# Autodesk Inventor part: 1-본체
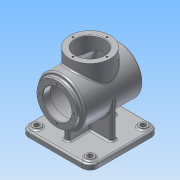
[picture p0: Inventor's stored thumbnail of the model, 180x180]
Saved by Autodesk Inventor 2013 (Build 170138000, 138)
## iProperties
Created: 2015-07
Part Number: 1-본체
Material: 알루미늄 6061
Document SubType Name: Modeling
Designer: Administrator
Density: 2.71 g/cm^3
Mass: 1279.26 g
Surface Area: 1271.88 cm^2
Volume: 472.05 cm^3
Author: Administrator
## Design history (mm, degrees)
sketch "스케치1"
  geometry: C1 r 45 at (0, 0); 1 further point
  constraints: 1 centre point, 1 coincident
  dimensions: "d0" = 90 diameter of C1
extrude "돌출1" new body sketch "스케치1" stored distance "d2" = 110; taper "d3" = 0 deg
node "작업 평면1"
sketch "스케치2"
  geometry: L1 (-50, 65)-(50, 65); L2 (65, 50)-(65, -50); L3 (50, -65)-(-50, -65); L4 (-65, -50)-(-65, 50); A1 r 15 centre (-50, 50) between (-50, 65) and (-65, 50); A2 r 15 centre (-50, -50) between (-65, -50) and (-50, -65); A3 r 15 centre (50, -50) between (50, -65) and (65, -50); A4 r 15 centre (50, 50) between (65, 50) and (50, 65); 6 further points
  constraints: 8 end point, 8 point on circle, 8 point on line, 8 tangent, 4 centre point, 3 equal radius, 2 parallel, 1 horizontal, 1 midpoint, 1 perpendicular, 1 vertical alignment
  dimensions: "d5" = 130 distance between parallel lines of L2 L4; "d7" = 65 distance from line of L3 point (0, 0); "d8" = 130 distance between parallel lines of L3 L1; "d11" = 15 radius of A1
extrude "돌출2" join sketch "스케치2" distance "d9" = 10; taper "d10" = 0 deg
sketch "스케치3"
  geometry: L1 (-50, -68)-(-65, -68) reference; L2 (50, -68)-(-50, -68) reference; L3 (65, -68)-(50, -68) reference; L4 (-45, -68)-(-45, 0); L5 (-45, 0)-(45, 0); L6 (45, 0)-(45, -68); C1 r 45 at (0, 0) reference; 2 further points
  constraints: 6 end point, 3 perpendicular, 2 point on line, 1 coincident, 1 midpoint, 1 tangent
  dimensions: "d14" = 68 distance between parallel lines of L2 L5
extrude "돌출3" join sketch "스케치3" stored distance "d16" = 10; taper "d17" = 0 deg
sketch "스케치4"
  geometry: L1 (-68, 50)-(-68, 65) reference; L2 (-68, -50)-(-68, 50) reference; L3 (-68, -65)-(-68, -50) reference; L4 (45, 55)-(-45, 55) reference; L5 (-45, -55)-(45, -55) reference; L6 (-68, 45)-(2, 45); L7 (2, 45)-(2, -45); L8 (2, -45)-(-68, -45); 2 further points
  constraints: 6 end point, 2 perpendicular, 2 point on line, 1 horizontal alignment, 1 midpoint, 1 parallel
  dimensions: "d18" = 90 distance between parallel lines of L8 L6; "d20" = 70 distance between parallel lines of L2 L7
extrude "돌출4" join sketch "스케치4" stored distance "d21" = 10; taper "d22" = 0 deg
sketch "스케치5"
  geometry: C1 r 38 at (0, 0); 1 further point
  constraints: 1 centre point, 1 coincident
  dimensions: "d23" = 76 diameter of C1
extrude "돌출5" join sketch "스케치5" distance "d25" = 62; taper "d26" = 0 deg
sketch "스케치6"
  geometry: C1 r 38 at (0, 0); 1 further point
  constraints: 1 centre point, 1 coincident
  dimensions: "d27" = 76 diameter of C1
extrude "돌출6" join sketch "스케치6" distance "d29" = 62; taper "d30" = 0 deg
sketch "스케치7"
  geometry: L1 (0, 48)-(0, -48); L2 (0, 48)-(40, 48); L3 (40, 48)-(40, -48); L4 (40, -48)-(0, -48); 2 further points
  constraints: 8 end point, 2 perpendicular, 1 coincident, 1 midpoint, 1 parallel, 1 vertical
  dimensions: "d67" = 96 distance of L1.start L1.end; "d69" = 80 diameter of L3 L1
revolve "회전1" sketch "스케치7" stored, may be unused: angle "d70" = 90 deg
hole "구멍5" diameter "d73" = 54; stored, may be unused: countersink angle "d77" = 90 deg, drill point angle "d79" = 118 deg; dims "d71" = 10, "d72" = 10, "d74" = 6, "d75" = 4, "d76" = 2, "d78" = 14
hole "구멍6" diameter "d82" = 54; stored, may be unused: countersink angle "d86" = 90 deg, drill point angle "d88" = 118 deg; dims "d80" = 10, "d81" = 10, "d83" = 6, "d84" = 4, "d85" = 2, "d87" = 30
sketch "스케치8"
  geometry: 2 further points
  constraints: 1 vertical alignment
  dimensions: "d89" = 32 distance of point (0, 0) point (0, 32)
hole "구멍7" sketch "스케치8" at (0, 32) diameter "d90" = 3.242; stored, may be unused: countersink angle "d94" = 90 deg, drill point angle "d96" = 118 deg; dims "d91" = 8, "d92" = 4, "d93" = 2, "d95" = 10
sketch "스케치9"
  geometry: 2 further points
  constraints: 1 vertical alignment
  dimensions: "d100" = 32 distance of point (0, 0) point (0, 32)
hole "구멍8" sketch "스케치9" at (0, 32) diameter "d101" = 3.242; stored, may be unused: countersink angle "d105" = 90 deg, drill point angle "d107" = 118 deg; dims "d102" = 8, "d103" = 4, "d104" = 2, "d106" = 10
sketch "스케치10"
  geometry: C1 r 7.5 at (-50, 50); C2 r 7.5 at (50, 50); C3 r 7.5 at (50, -50); C4 r 7.5 at (-50, -50); 1 further point
  constraints: 4 centre point, 3 equal radius, 2 horizontal alignment, 2 vertical alignment
  dimensions: "d111" = 100 distance of C2.centre C1.centre; "d113" = 50 horizontal distance of C2.centre point (0, 0); "d114" = 100 distance of C3.centre C2.centre; "d115" = 50 horizontal distance of C3.centre point (0, 0); "d116" = 15 diameter of C2
extrude "돌출7" join sketch "스케치10" distance "d117" = 3; taper "d118" = 0 deg
hole "구멍9" diameter "d121" = 10; stored, may be unused: countersink angle "d125" = 90 deg, drill point angle "d127" = 118 deg; dims "d119" = 10, "d120" = 10, "d122" = 10, "d123" = 4, "d124" = 2, "d126" = 10
hole "구멍10" diameter "d130" = 10; stored, may be unused: countersink angle "d134" = 90 deg, drill point angle "d136" = 118 deg; dims "d128" = 10, "d129" = 10, "d131" = 10, "d132" = 4, "d133" = 2, "d135" = 10
hole "구멍11" diameter "d139" = 10; stored, may be unused: countersink angle "d143" = 90 deg, drill point angle "d145" = 118 deg; dims "d137" = 10, "d138" = 10, "d140" = 10, "d141" = 4, "d142" = 2, "d144" = 10
hole "구멍12" diameter "d148" = 10; stored, may be unused: countersink angle "d152" = 90 deg, drill point angle "d154" = 118 deg; dims "d146" = 10, "d147" = 10, "d149" = 10, "d150" = 4, "d151" = 2, "d153" = 10
sketch "스케치11"
  geometry: L1 (-23.291, 3.588)-(23.291, 3.588); L2 (23.291, 3.588)-(23.291, -3.588); L3 (23.291, -3.588)-(-23.291, -3.588); L4 (-23.291, -3.588)-(-23.291, 3.588); 4 further points
  constraints: 2 midpoint, 1 coincident, 1 horizontal alignment, 1 vertical, 1 vertical alignment, 2 other
  dimensions: "d155" = 46.58163 distance between parallel lines of L2 L4; "d156" = 7.17576 distance between parallel lines of L3 L1
feature "엠보싱1" sketch "스케치11" dims "d0" = 90, "d157" = 0.5, "d158" = 0
chamfer "모따기1" distance "d159" = 1; stored, may be unused: second distance "d160" = 2, angle "d161" = 45 deg
fillet "모깎기1" dims "d162" = 3
fillet "모깎기2" dims "d163" = 3
fillet "모깎기3" dims "d164" = 3
fillet "모깎기4" dims "d165" = 3
fillet "모깎기5" dims "d166" = 3
fillet "모깎기6" dims "d167" = 3
fillet "모깎기7" dims "d168" = 3
fillet "모깎기8" dims "d169" = 3
fillet "모깎기9" dims "d170" = 3
fillet "모깎기10" dims "d171" = 3
fillet "모깎기11" dims "d172" = 3
node "솔리드1"
pattern_circular "원형 패턴1" dims angle "d98" = 360 deg
pattern_circular "원형 패턴2" dims angle "d109" = 360 deg
other parameters: "d4" = -78
